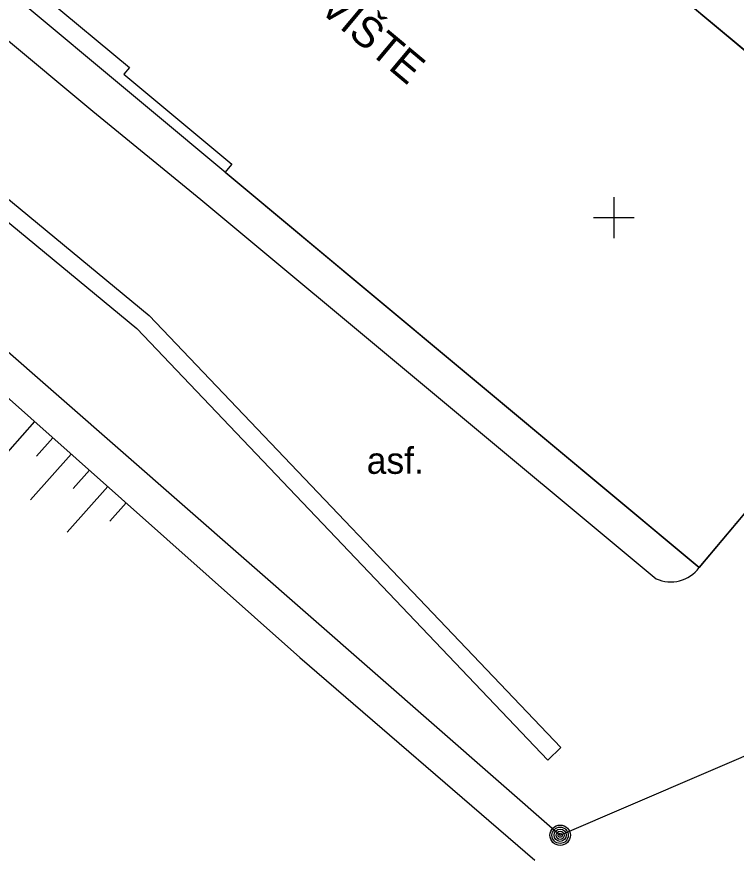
# Model space of a CAD drawing. Extents: x -438200 to -437954, y -1133133 to -1132850.
# Drawn here: x -438114.64 to -438097, y -1133015.76 to -1132995.08 of the extents above; entities that cross this region are included whole.
import ezdxf

# ---------------------------------------------------------------- set-up
doc = ezdxf.new("R2010")
doc.units = 0
for name, color, linetype in [('Vrstva 1', 7, 'Continuous'), ('Vrstva 10', 7, 'Continuous'), ('Vrstva 11', 7, 'Continuous'), ('Vrstva 14', 7, 'Continuous'), ('Vrstva 15', 7, 'Continuous'), ('Vrstva 25', 7, 'Continuous'), ('Vrstva 40', 7, 'Continuous'), ('Vrstva 5', 7, 'Continuous'), ('Vrstva 55', 7, 'Continuous'), ('Vrstva 58', 7, 'Continuous'), ('Vrstva 61', 7, 'Continuous')]:
    doc.layers.add(name, color=color, linetype=linetype)

msp = doc.modelspace()

# ---------------------------------------------------------------- linework, layer by layer
at = {"layer": 'Vrstva 1'}
for p, q in [((-438112.774, -1132997.389), (-438112.774, -1132997.389)), ((-438109.538, -1132998.894), (-438109.538, -1132998.894)), ((-438110.127, -1132999.558), (-438110.127, -1132999.558)), ((-438111.395, -1133002.396), (-438111.395, -1133002.396)), ((-438111.732, -1133002.689), (-438111.732, -1133002.689)), ((-438097.047, -1133007.494), (-438097.047, -1133007.494)), ((-438097.908, -1133008.583), (-438097.908, -1133008.583)), ((-438098.962, -1133008.857), (-438098.962, -1133008.857)), ((-438107.695, -1133010.79), (-438107.695, -1133010.79)), ((-438101.295, -1133012.998), (-438101.295, -1133012.998)), ((-438101.573, -1133013.279), (-438101.573, -1133013.279)), ((-438101.339, -1133013.202), (-438101.339, -1133013.202)), ((-438101.316, -1133015.148), (-438101.316, -1133015.148))]:
    msp.add_line(p, q, dxfattribs=at)
at = {"layer": 'Vrstva 10'}
msp.add_lwpolyline([(-438136.916, -1132976.04), (-438130.815, -1132968.777), (-438110.909, -1132985.383), (-438109.206, -1132983.342), (-438101.698, -1132989.616), (-438102.771, -1132990.9), (-438091.189, -1133000.578), (-438097.908, -1133008.583)], close=True, dxfattribs=at)
msp.add_lwpolyline([(-438136.916, -1132976.04), (-438130.815, -1132968.777), (-438110.909, -1132985.383), (-438109.206, -1132983.342), (-438101.698, -1132989.616), (-438102.771, -1132990.9), (-438091.189, -1133000.578), (-438097.908, -1133008.583)], close=True, dxfattribs=at)
at = {"layer": 'Vrstva 11'}
for points in [[(-438138.792, -1132977.357), (-438140.226, -1132979.081), (-438130.239, -1132987.383), (-438111.696, -1133002.719), (-438101.614, -1133013.302)], [(-438138.453, -1132977.639), (-438139.605, -1132979.024), (-438129.958, -1132987.044), (-438111.395, -1133002.396), (-438101.295, -1133012.998)], [(-438128.485, -1132984.283), (-438112.774, -1132997.389), (-438110.127, -1132999.558), (-438098.962, -1133008.857)], [(-438101.614, -1133013.302), (-438101.295, -1133012.998)]]:
    msp.add_lwpolyline(points, dxfattribs=at)
msp.add_arc((-438098.606, -1133008.062), 0.871, 245.8831, 323.2613, dxfattribs=at)
at = {"layer": 'Vrstva 14'}
msp.add_lwpolyline([(-438140.54, -1132981.557), (-438107.695, -1133010.79), (-438101.937, -1133015.758)], dxfattribs=at)
at = {"layer": 'Vrstva 15'}
for p, q in [((-438114.202, -1133004.999), (-438115.199, -1133006.119)), ((-438113.754, -1133005.398), (-438114.152, -1133005.846)), ((-438113.305, -1133005.797), (-438114.303, -1133006.917)), ((-438112.857, -1133006.195), (-438113.256, -1133006.644)), ((-438112.409, -1133006.594), (-438113.406, -1133007.715)), ((-438111.961, -1133006.993), (-438112.36, -1133007.441))]:
    msp.add_line(p, q, dxfattribs=at)
at = {"layer": 'Vrstva 25'}
for radius in [0.25, 0.2, 0.15, 0.1, 0.05]:
    msp.add_circle((-438101.316, -1133015.148), radius, dxfattribs=at)
at = {"layer": 'Vrstva 5'}
for p, q in [((-438091.189, -1133000.578), (-438102.771, -1132990.9)), ((-438116.463, -1132992.491), (-438111.878, -1132996.316)), ((-438111.878, -1132996.316), (-438112.013, -1132996.477)), ((-438112.013, -1132996.477), (-438109.364, -1132998.687)), ((-438109.364, -1132998.687), (-438109.538, -1132998.894)), ((-438109.531, -1132998.886), (-438097.908, -1133008.583)), ((-438097.908, -1133008.583), (-438091.189, -1133000.578)), ((-438097.908, -1133008.583), (-438097.908, -1133008.583))]:
    msp.add_line(p, q, dxfattribs=at)
at = {"layer": 'Vrstva 58'}
msp.add_lwpolyline([(-438130.562, -1132992.413), (-438128.998, -1132990.895), (-438101.316, -1133015.148), (-438080.005, -1133005.995)], dxfattribs=at)
at = {"layer": 'Vrstva 61'}
for p, q in [((-438100, -1132999.5), (-438100, -1133000.5)), ((-438100.5, -1133000), (-438099.5, -1133000))]:
    msp.add_line(p, q, dxfattribs=at)

# ---------------------------------------------------------------- texts
at = {"layer": 'Vrstva 40'}
msp.add_text('asf.', height=0.65, dxfattribs=at).set_placement((-438106.058, -1133006.283))
at = {"layer": 'Vrstva 55'}
msp.add_text('AUTOBUSOVÉ STANOVIŠTE', height=0.74999, rotation=320.1027, dxfattribs=at).set_placement((-438115.474, -1132988.046))

doc.saveas('drawing.dxf')
